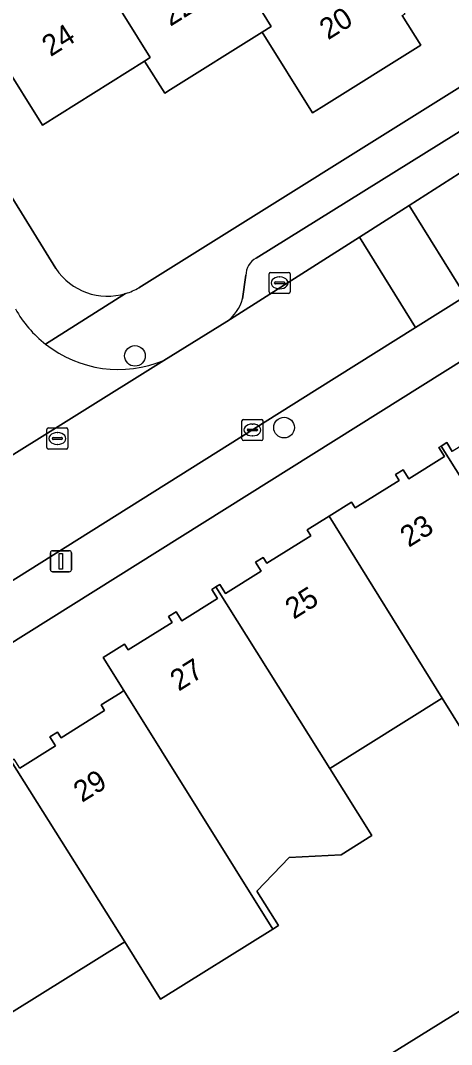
# Model space of a CAD drawing. Extents: x 157767 to 159172, y 387839 to 389425.
# Drawn here: x 158588.4 to 158608.84, y 388022.11 to 388070.65 of the extents above; entities that cross this region are included whole.
import ezdxf

# ---------------------------------------------------------------- set-up
doc = ezdxf.new("R2010")
doc.units = 0
for name, color, linetype in [('IMGEO_Boom', 7, 'Continuous'), ('IMGEO_Erf', 7, 'Continuous'), ('IMGEO_Kolk', 7, 'Continuous'), ('IMGEO_Lichtmast', 7, 'Continuous'), ('IMGEO_Pand', 7, 'Continuous'), ('IMGEO_Pand_nummerreeks', 7, 'Continuous'), ('IMGEO_Parkeervlak_open', 7, 'Continuous'), ('IMGEO_Rijbaan_lokaal_open', 7, 'Continuous'), ('IMGEO_Rioolput', 7, 'Continuous'), ('IMGEO_Voetpad_open', 7, 'Continuous')]:
    doc.layers.add(name, color=color, linetype=linetype)

msp = doc.modelspace()

# ---------------------------------------------------------------- linework, layer by layer
at = {"layer": 'IMGEO_Boom'}
for centre in [(158593.83, 388054.748), (158600.899, 388051.349)]:
    msp.add_circle(centre, 0.489, dxfattribs=at)
at = {"layer": 'IMGEO_Erf'}
for points in [[(158594.021, 388057.981), (158645.347, 388090.085)], [(158606.501, 388070.878), (158607.378, 388069.481), (158602.662, 388066.524), (158602.252, 388066.267), (158599.852, 388070.093), (158595.508, 388067.368), (158595.241, 388067.201), (158594.284, 388068.725), (158589.446, 388065.691), (158587.528, 388068.75), (158584.968, 388067.145), (158590.08, 388058.884)], [(158612.65, 388056.606), (158587.736, 388040.994)], [(158588.375, 388035.208), (158590.059, 388036.26), (158589.791, 388036.685), (158590.156, 388036.913), (158590.326, 388036.64), (158592.393, 388037.933), (158592.222, 388038.205), (158593.123, 388038.768), (158593.308, 388038.884), (158592.326, 388040.458), (158593.338, 388041.091), (158593.509, 388040.817), (158595.59, 388042.118), (158595.418, 388042.392), (158595.786, 388042.621), (158596.054, 388042.193), (158597.749, 388043.254), (158597.48, 388043.681), (158597.665, 388043.796), (158597.848, 388043.91), (158598.116, 388043.482), (158599.81, 388044.542), (158599.542, 388044.969), (158599.909, 388045.199), (158600.08, 388044.924), (158602.162, 388046.226), (158601.99, 388046.5), (158603.032, 388047.152), (158604.097, 388047.818), (158604.267, 388047.544), (158606.348, 388048.845), (158606.176, 388049.119), (158606.544, 388049.348), (158606.812, 388048.92), (158608.507, 388049.981), (158608.238, 388050.408), (158608.344, 388050.474), (158608.606, 388050.638), (158608.874, 388050.209)], [(158604.619, 388020.821), (158609.949, 388024.149), (158615.304, 388027.493), (158613.812, 388029.857), (158616.2, 388031.365), (158617.7, 388028.989), (158620.6, 388030.8), (158621.923, 388028.682), (158626.461, 388031.515), (158627.361, 388032.074), (158620.707, 388042.743), (158615.388, 388039.416), (158609.958, 388036.019), (158608.4, 388038.523), (158603.064, 388035.187), (158605.057, 388032.01), (158603.604, 388031.102), (158601.147, 388030.977), (158599.613, 388029.374), (158600.633, 388027.743), (158600.362, 388027.574), (158595.048, 388024.252), (158593.345, 388026.976), (158587.983, 388023.623)]]:
    msp.add_lwpolyline(points, dxfattribs=at)
for centre, radius, start, end in [((158592.532, 388060.534), 2.955, 213.9322, 286.8348), ((158592.511, 388060.58), 3.006, 286.9619, 300.1543)]:
    msp.add_arc(centre, radius, start, end, dxfattribs=at)
at = {"layer": 'IMGEO_Kolk'}
for p, q in [((158600.261, 388058.708), (158601.113, 388058.708)), ((158600.186, 388057.782), (158600.186, 388058.634)), ((158600.445, 388058.202), (158600.445, 388058.214)), ((158600.488, 388058.251), (158600.886, 388058.251)), ((158600.674, 388058.488), (158600.699, 388058.488)), ((158600.929, 388058.214), (158600.929, 388058.202)), ((158601.187, 388058.634), (158601.187, 388057.782)), ((158601.113, 388057.708), (158600.261, 388057.708)), ((158600.883, 388058.165), (158600.485, 388058.165)), ((158600.697, 388057.928), (158600.672, 388057.928)), ((158598.898, 388050.813), (158598.898, 388051.665)), ((158598.973, 388051.739), (158599.825, 388051.739)), ((158599.386, 388051.519), (158599.411, 388051.519)), ((158599.899, 388051.665), (158599.899, 388050.813)), ((158599.157, 388051.233), (158599.157, 388051.245)), ((158599.595, 388051.196), (158599.197, 388051.196)), ((158599.2, 388051.282), (158599.598, 388051.282)), ((158599.409, 388050.959), (158599.384, 388050.959)), ((158599.641, 388051.245), (158599.641, 388051.233)), ((158599.825, 388050.739), (158598.973, 388050.739))]:
    msp.add_line(p, q, dxfattribs=at)
for points in [[(158600.261, 388058.708), (158601.113, 388058.708)], [(158600.186, 388057.782), (158600.186, 388058.634)], [(158601.187, 388058.634), (158601.187, 388057.782)], [(158601.113, 388057.708), (158600.261, 388057.708)], [(158598.898, 388050.813), (158598.898, 388051.665)], [(158598.973, 388051.739), (158599.825, 388051.739)], [(158599.899, 388051.665), (158599.899, 388050.813)], [(158599.825, 388050.739), (158598.973, 388050.739)]]:
    msp.add_lwpolyline(points, dxfattribs=at)
for centre, radius, start, end in [((158600.263, 388058.632), 0.0765, 91.552, 178.448), ((158600.263, 388058.632), 0.0765, 91.552, 178.448), ((158601.111, 388058.632), 0.0765, 1.552, 88.448), ((158601.111, 388058.632), 0.0765, 1.552, 88.448), ((158600.485, 388058.211), 0.0403, 85.8775, 175.7526), ((158600.482, 388058.201), 0.0366, 178.938, 274.7102), ((158600.886, 388058.208), 0.043, 264.8664, 352.4533), ((158600.89, 388058.213), 0.0386, 1.7309, 96.639), ((158600.263, 388057.784), 0.0765, 181.552, 268.448), ((158600.263, 388057.784), 0.0765, 181.552, 268.448), ((158601.111, 388057.784), 0.0765, 271.552, 358.448), ((158601.111, 388057.784), 0.0765, 271.552, 358.448), ((158598.975, 388051.663), 0.0765, 91.552, 178.448), ((158598.975, 388051.663), 0.0765, 91.552, 178.448), ((158599.823, 388051.663), 0.0765, 1.552, 88.448), ((158599.823, 388051.663), 0.0765, 1.552, 88.448), ((158599.197, 388051.242), 0.0403, 85.8775, 175.7526), ((158599.194, 388051.232), 0.0366, 178.938, 274.7102), ((158599.598, 388051.239), 0.043, 264.8664, 352.4533), ((158599.602, 388051.244), 0.0386, 1.7309, 96.639), ((158598.975, 388050.815), 0.0765, 181.552, 268.448), ((158598.975, 388050.815), 0.0765, 181.552, 268.448), ((158599.823, 388050.815), 0.0765, 271.552, 358.448), ((158599.823, 388050.815), 0.0765, 271.552, 358.448)]:
    msp.add_arc(centre, radius, start, end, dxfattribs=at)
for centre, major_axis, ratio, start_param, end_param in [((158600.673, 388058.208), (-0.387, 0.002), 0.722429, 4.712389, 7.853982), ((158600.698, 388058.208), (-0.39, 0.002), 0.717154, 1.570796, 4.712389), ((158599.385, 388051.239), (-0.387, 0.002), 0.722429, 4.712389, 7.853982), ((158599.41, 388051.239), (-0.39, 0.002), 0.717154, 1.570796, 4.712389)]:
    msp.add_ellipse(centre, major_axis=major_axis, ratio=ratio, start_param=start_param, end_param=end_param, dxfattribs=at)
at = {"layer": 'IMGEO_Lichtmast'}
for p, q in [((158589.824, 388044.614), (158589.824, 388045.414)), ((158589.824, 388045.414), (158589.824, 388044.614)), ((158589.924, 388045.514), (158590.714, 388045.514)), ((158590.714, 388045.514), (158589.924, 388045.514)), ((158590.814, 388045.414), (158590.814, 388044.614)), ((158590.814, 388044.614), (158590.814, 388045.414)), ((158590.714, 388044.514), (158589.924, 388044.514)), ((158589.924, 388044.514), (158590.714, 388044.514))]:
    msp.add_line(p, q, dxfattribs=at)
msp.add_lwpolyline([(158590.244, 388045.389), (158590.394, 388045.389), (158590.394, 388044.639), (158590.244, 388044.639), (158590.244, 388045.389)], dxfattribs=at)
for centre, start, end in [((158589.924, 388045.414), 90, 180), ((158589.924, 388045.414), 90, 180), ((158590.714, 388045.414), 0, 90), ((158590.714, 388045.414), 360, 90), ((158589.924, 388044.614), 180, 270), ((158589.924, 388044.614), 180, 270), ((158590.714, 388044.614), 270, 0), ((158590.714, 388044.614), 270, 0)]:
    msp.add_arc(centre, 0.1, start, end, dxfattribs=at)
at = {"layer": 'IMGEO_Pand'}
for points in [[(158602.235, 388078.12), (158599.864, 388081.968), (158595.324, 388079.121), (158595.012, 388078.925), (158597.544, 388074.82), (158600.291, 388070.368), (158599.852, 388070.093), (158602.252, 388066.267), (158602.662, 388066.524), (158607.378, 388069.481), (158606.501, 388070.878), (158606.643, 388070.967)], [(158595.012, 388078.925), (158590.193, 388075.903), (158594.557, 388068.896), (158594.284, 388068.725), (158595.241, 388067.201), (158595.508, 388067.368), (158599.852, 388070.093), (158600.291, 388070.368), (158597.544, 388074.82)], [(158590.193, 388075.903), (158585.3, 388072.835), (158584.145, 388074.678), (158581.379, 388072.944), (158581.281, 388072.883), (158584.968, 388067.145), (158587.528, 388068.75), (158589.446, 388065.691), (158594.284, 388068.725), (158594.557, 388068.896)], [(158608.344, 388050.474), (158613.748, 388041.867), (158615.388, 388039.416), (158620.707, 388042.743), (158620.898, 388042.862), (158619.908, 388044.446), (158613.947, 388053.977), (158612.748, 388053.227), (158612.919, 388052.953), (158610.839, 388051.651), (158610.668, 388051.926), (158610.3, 388051.697), (158610.569, 388051.269), (158608.874, 388050.209), (158608.606, 388050.638)], [(158608.344, 388050.474), (158608.238, 388050.408), (158608.507, 388049.981), (158606.812, 388048.92), (158606.544, 388049.348), (158606.176, 388049.119), (158606.348, 388048.845), (158604.267, 388047.544), (158604.097, 388047.818), (158603.032, 388047.152), (158608.4, 388038.523), (158609.958, 388036.019), (158615.388, 388039.416), (158613.748, 388041.867)], [(158597.665, 388043.796), (158603.064, 388035.187), (158608.4, 388038.523), (158603.032, 388047.152), (158601.99, 388046.5), (158602.162, 388046.226), (158600.08, 388044.924), (158599.909, 388045.199), (158599.542, 388044.969), (158599.81, 388044.542), (158598.116, 388043.482), (158597.848, 388043.91)], [(158597.665, 388043.796), (158597.48, 388043.681), (158597.749, 388043.254), (158596.054, 388042.193), (158595.786, 388042.621), (158595.418, 388042.392), (158595.59, 388042.118), (158593.509, 388040.817), (158593.338, 388041.091), (158592.326, 388040.458), (158593.308, 388038.884), (158600.362, 388027.574), (158600.633, 388027.743), (158599.613, 388029.374), (158601.147, 388030.977), (158603.604, 388031.102), (158605.057, 388032.01), (158603.064, 388035.187)], [(158593.308, 388038.884), (158593.123, 388038.768), (158592.222, 388038.205), (158592.393, 388037.933), (158590.326, 388036.64), (158590.156, 388036.913), (158589.791, 388036.685), (158590.059, 388036.26), (158588.375, 388035.208), (158588.109, 388035.633), (158587.959, 388035.54), (158593.345, 388026.976), (158595.048, 388024.252), (158600.362, 388027.574)], [(158587.983, 388023.623), (158593.345, 388026.976), (158587.959, 388035.54), (158587.744, 388035.406), (158588.011, 388034.981), (158586.327, 388033.928), (158586.061, 388034.353), (158585.696, 388034.125), (158585.866, 388033.853), (158583.799, 388032.561), (158583.63, 388032.834), (158582.614, 388032.197)], [(158604.619, 388020.821), (158607.488, 388016.275), (158612.831, 388019.611), (158609.949, 388024.149)]]:
    msp.add_lwpolyline(points, close=True, dxfattribs=at)
at = {"layer": 'IMGEO_Parkeervlak_open'}
for points in [[(158598.186, 388056.371), (158604.468, 388060.381), (158606.82, 388061.883), (158615.518, 388067.436), (158634.377, 388079.187)], [(158631.617, 388079.33), (158599.57, 388059.375)], [(158599.088, 388058.567), (158598.934, 388057.454)]]:
    msp.add_lwpolyline(points, dxfattribs=at)
for centre, radius, start, end in [((158599.979, 388058.583), 0.891, 117.328, 181.0369), ((158596.928, 388058.04), 2.09, 307.0127, 343.7236)]:
    msp.add_arc(centre, radius, start, end, dxfattribs=at)
at = {"layer": 'IMGEO_Rijbaan_lokaal_open'}
for points in [[(158640.372, 388082.674), (158634.377, 388079.187), (158615.518, 388067.436), (158606.82, 388061.883), (158609.497, 388057.581), (158610.247, 388058.053), (158619.775, 388064.037), (158629.892, 388070.391), (158639.978, 388076.645)], [(158582.332, 388046.529), (158582.556, 388046.64), (158595.192, 388054.536)]]:
    msp.add_lwpolyline(points, dxfattribs=at)
for points in [[(158606.82, 388061.883), (158604.468, 388060.381), (158607.134, 388056.097), (158609.497, 388057.581)], [(158602.47, 388053.168), (158607.134, 388056.097), (158604.468, 388060.381), (158598.186, 388056.371), (158595.192, 388054.536), (158582.556, 388046.64), (158582.332, 388046.529), (158565.577, 388036.046), (158560.3, 388032.761), (158562.987, 388028.446), (158574.586, 388035.66), (158586.389, 388043.071)]]:
    msp.add_lwpolyline(points, close=True, dxfattribs=at)
for centre, radius, start, end in [((158593.035, 388059.692), 5.58, 209.1561, 231.9393), ((158593.045, 388059.699), 5.592, 231.9126, 292.5817)]:
    msp.add_arc(centre, radius, start, end, dxfattribs=at)
at = {"layer": 'IMGEO_Rioolput'}
for p, q in [((158589.653, 388050.405), (158589.653, 388051.257)), ((158589.728, 388051.331), (158590.58, 388051.331)), ((158590.141, 388051.111), (158590.166, 388051.111)), ((158590.654, 388051.257), (158590.654, 388050.405)), ((158589.912, 388050.825), (158589.912, 388050.837)), ((158590.35, 388050.788), (158589.952, 388050.788)), ((158589.955, 388050.874), (158590.353, 388050.874)), ((158590.164, 388050.551), (158590.139, 388050.551)), ((158590.396, 388050.837), (158590.396, 388050.825)), ((158590.58, 388050.331), (158589.728, 388050.331))]:
    msp.add_line(p, q, dxfattribs=at)
for points in [[(158589.653, 388050.405), (158589.653, 388051.257)], [(158589.728, 388051.331), (158590.58, 388051.331)], [(158590.654, 388051.257), (158590.654, 388050.405)], [(158590.58, 388050.331), (158589.728, 388050.331)]]:
    msp.add_lwpolyline(points, dxfattribs=at)
for centre, radius, start, end in [((158589.73, 388051.255), 0.0765, 91.552, 178.448), ((158589.73, 388051.255), 0.0765, 91.552, 178.448), ((158590.578, 388051.255), 0.0765, 1.552, 88.448), ((158590.578, 388051.255), 0.0765, 1.552, 88.448), ((158589.952, 388050.834), 0.0403, 85.8775, 175.7526), ((158589.949, 388050.824), 0.0366, 178.938, 274.7102), ((158590.353, 388050.831), 0.043, 264.8664, 352.4533), ((158590.357, 388050.836), 0.0386, 1.7309, 96.639), ((158589.73, 388050.407), 0.0765, 181.552, 268.448), ((158589.73, 388050.407), 0.0765, 181.552, 268.448), ((158590.578, 388050.407), 0.0765, 271.552, 358.448), ((158590.578, 388050.407), 0.0765, 271.552, 358.448)]:
    msp.add_arc(centre, radius, start, end, dxfattribs=at)
for centre, major_axis, ratio, start_param, end_param in [((158590.14, 388050.831), (-0.387, 0.002), 0.722429, 4.712389, 7.853982), ((158590.165, 388050.831), (-0.39, 0.002), 0.717154, 1.570796, 4.712389)]:
    msp.add_ellipse(centre, major_axis=major_axis, ratio=ratio, start_param=start_param, end_param=end_param, dxfattribs=at)
at = {"layer": 'IMGEO_Voetpad_open'}
for points in [[(158686.368, 388027.385), (158661.715, 388067.158), (158659.117, 388071.321), (158646.863, 388091.033), (158646.674, 388090.915), (158645.347, 388090.085), (158594.021, 388057.981)], [(158599.57, 388059.375), (158631.617, 388079.33)], [(158590.08, 388058.884), (158584.968, 388067.145)], [(158545.154, 388012.431), (158548.372, 388014.479), (158586.39, 388038.074), (158587.736, 388040.994), (158612.65, 388056.606), (158611.489, 388058.243), (158610.518, 388057.633), (158610.247, 388058.053), (158609.497, 388057.581), (158607.134, 388056.097), (158602.47, 388053.168), (158586.389, 388043.071)], [(158598.934, 388057.454), (158599.088, 388058.567)], [(158589.595, 388055.298), (158593.388, 388057.705)], [(158593.388, 388057.705), (158589.595, 388055.298)], [(158595.192, 388054.536), (158598.186, 388056.371)]]:
    msp.add_lwpolyline(points, dxfattribs=at)
for centre, radius, start, end in [((158599.979, 388058.583), 0.891, 117.328, 181.0369), ((158592.532, 388060.534), 2.955, 213.9322, 286.8348), ((158592.511, 388060.58), 3.006, 286.9619, 300.1543), ((158596.928, 388058.04), 2.09, 307.0127, 343.7236), ((158593.035, 388059.692), 5.58, 209.1561, 231.9393), ((158593.045, 388059.699), 5.592, 231.9126, 292.5817)]:
    msp.add_arc(centre, radius, start, end, dxfattribs=at)

# ---------------------------------------------------------------- texts
at = {"layer": 'IMGEO_Pand_nummerreeks'}
for s, rotation, p in [('22', 32.0971, (158595.505, 388070.342)), ('20', 32.0856, (158602.983, 388069.7)), ('24', 32.0914, (158589.826, 388068.905)), ('23', 32.0169, (158606.807, 388045.645)), ('25', 32.0167, (158601.355, 388042.236)), ('27', 32.0169, (158595.903, 388038.827)), ('29', 31.7877, (158591.317, 388033.557))]:
    msp.add_text(s, height=1, rotation=rotation, dxfattribs=at).set_placement(p)

doc.saveas('drawing.dxf')
